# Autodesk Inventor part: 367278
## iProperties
Created: 2006-09
Part Number: 367278
Material: 8.8 vz
Description: Zylinderschraube
Vendor: Autodesk Inc.
Document SubType Name: Modeling
Standard: DIN 912
Designer: I.Baliuc
Standards Organization: DIN
Language: de-DE
Size Designation: M8 x 12
Categories: <MemberInstance Version="R10.0.0"><Categories><Category DisplayName="Schrauben" InternalName="e4da775c-781d-43d5-af7c-5136215cf5a6" Mnemonic="FSTN"><Category Di
Density: 7.85 g/cm^3
Mass: 11.8026 g
Surface Area: 9.59043 cm^2
Volume: 1.50352 cm^3
Abmessung: M8 x 12
Author: T.Messerschmitt
Comments: DIN 912 - M8 x 12
Revision Number: 367278
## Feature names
1. Körper [Revolution]
2. Loch [Extrusion]
3. Rundung1 [Fillet]
4. Fase1 [Chamfer]
